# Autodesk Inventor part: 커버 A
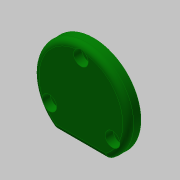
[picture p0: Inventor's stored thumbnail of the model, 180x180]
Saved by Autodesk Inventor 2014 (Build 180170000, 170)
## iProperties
Created: 2020-04
Part Number: 커버 A
Material: 알루미늄 6061
Document SubType Name: Modeling
Designer: mduedu
Density: 2.71 g/cm^3
Mass: 30.8964 g
Surface Area: 61.0159 cm^2
Volume: 11.4009 cm^3
Appearance: Dark Green
Author: mduedu
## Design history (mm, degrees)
sketch "스케치1"
  geometry: C1 r 26 at (0, 0); 1 further point
  constraints: 1 centre point, 1 coincident
  dimensions: "d0" = 52 diameter of C1
extrude "돌출1" new body sketch "스케치1" distance "d1" = 7; taper "d2" = 0 deg
sketch "스케치2"
  geometry: L1 (-14.62, -21.5)-(14.62, -21.5); A1 r 26 centre (0, 0) between (-14.62, -21.5) and (14.62, -21.5) reference; 1 further point
  constraints: 2 end point, 2 point on circle, 1 horizontal
  dimensions: "d3" = 21.5 distance from line of L1 point (0, 0)
extrude "돌출2" cut sketch "스케치2" stored distance "d4" = 7; taper "d5" = 0 deg
fillet "모깎기1" dims "d6" = 3
fillet "모깎기2" dims "d7" = 3
sketch "스케치3" dims "d8" = 40
  geometry: 3 further points
  constraints: 2 vertical alignment, 1 coincident, 2 other
hole "구멍1" sketch "스케치3" at (0, 20) diameter "d9" = 4.5; stored, may be unused: countersink angle "d13" = 90 deg, drill point angle "d15" = 118 deg; dims "d10" = 6, "d11" = 8, "d12" = 4.4, "d14" = 8
sketch "스케치4"
  geometry: C1 r 16 at (0, 0); 1 further point
  constraints: 1 centre point, 1 coincident
  dimensions: "d19" = 32 diameter of C1
extrude "돌출3" join sketch "스케치4" distance "d20" = 3; taper "d21" = 0 deg
sketch "스케치5"
  geometry: C1 r 14 at (0, 0); 1 further point
  constraints: 1 centre point, 1 coincident
  dimensions: "d22" = 28 diameter of C1
extrude "돌출4" cut sketch "스케치5" distance "d23" = 7; taper "d24" = 0 deg
fillet "모깎기3" dims "d25" = 3
chamfer "모따기1" distance "d26" = 0.5; stored, may be unused: second distance "d27" = 2, angle "d28" = 45 deg
node "솔리드1"
pattern_circular "원형 패턴1" dims angle "d17" = 360 deg
node "투영된 루프1"
